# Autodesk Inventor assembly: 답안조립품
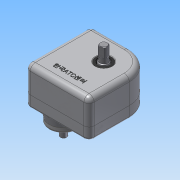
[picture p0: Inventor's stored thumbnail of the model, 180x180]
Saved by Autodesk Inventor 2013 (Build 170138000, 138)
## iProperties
Created: 2015-11
Part Number: 답안조립품
Document SubType Name: Assembly
Designer: Administrator
Author: Administrator
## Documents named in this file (13)
- C:\Users\Administrator\Desktop\Inventor2급\2급\공용부품_20151104_2\답안조립품.iam
- C:\Users\Administrator\Desktop\Inventor2급\2급\공용부품_20151104_2\본체.ipt
- C:\Users\Administrator\Desktop\Inventor2급\2급\공용부품_20151104_2\M3 x 0.5.ipt
- C:\Users\Administrator\Desktop\Inventor2급\2급\공용부품_20151104_2\M4 x 0.7.ipt
- C:\Users\Administrator\Desktop\Inventor2급\2급\공용부품_20151104_2\로드 축.ipt
- C:\Users\Administrator\Desktop\Inventor2급\2급\공용부품_20151104_2\로드.ipt
- C:\Users\Administrator\Desktop\Inventor2급\2급\공용부품_20151104_2\베어링 6001.ipt
- C:\Users\Administrator\Desktop\Inventor2급\2급\공용부품_20151104_2\베어링 6002.ipt
- C:\Users\Administrator\Desktop\Inventor2급\2급\공용부품_20151104_2\앞커버.ipt
- C:\Users\Administrator\Desktop\Inventor2급\2급\공용부품_20151104_2\오일실 12 x 22.ipt
- C:\Users\Administrator\Desktop\Inventor2급\2급\공용부품_20151104_2\오일실 15 x 25.ipt
- C:\Users\Administrator\Desktop\Inventor2급\2급\공용부품_20151104_2\축 커버.ipt
- C:\Users\Administrator\Desktop\Inventor2급\2급\공용부품_20151104_2\편심 축.ipt
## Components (9 placed, 2 different names)
1. M4 x 0.7:1
2. M4 x 0.7:2
3. M4 x 0.7:3
4. M4 x 0.7:5
5. M4 x 0.7:6
6. M3 x 0.5:1
7. M3 x 0.5:2
8. M3 x 0.5:3
9. M3 x 0.5:4
